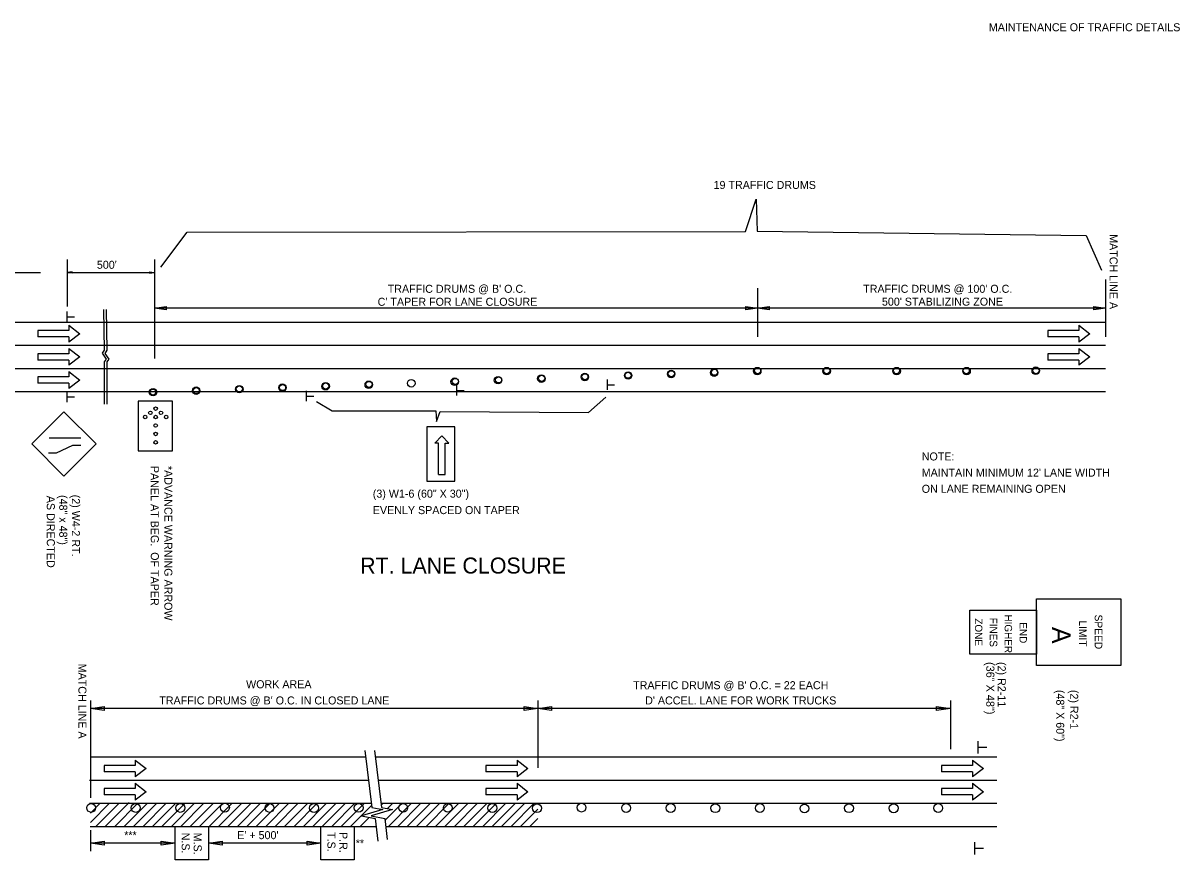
# Model space of a CAD drawing. Extents: x 1373848 to 1374003, y 380642 to 381248.
# Drawn here: x 1373915.2 to 1374001.9, y 381182.7 to 381245.5 of the extents above; entities that cross this region are included whole.
import ezdxf

# ---------------------------------------------------------------- set-up
doc = ezdxf.new("R2010")
doc.units = 0
doc.layers.add('Default', color=7, linetype='Continuous')
doc.layers.add('G-ANNO-TEXT', color=7, linetype='Continuous')

msp = doc.modelspace()

# ---------------------------------------------------------------- linework, layer by layer
at = {"layer": 'Default'}
for p, q in [((1373918.516, 381227.732), (1373918.516, 381224.211)), ((1373925.063, 381227.732), (1373925.063, 381220.318)), ((1373911.3, 381226.753), (1373916.518, 381226.753)), ((1373918.891, 381226.809), (1373918.516, 381226.753)), ((1373918.516, 381226.753), (1373925.063, 381226.753)), ((1373918.891, 381226.697), (1373918.516, 381226.753)), ((1373918.891, 381226.8), (1373918.579, 381226.753)), ((1373918.891, 381226.706), (1373918.579, 381226.753)), ((1373918.891, 381226.79), (1373918.643, 381226.753)), ((1373918.891, 381226.716), (1373918.643, 381226.753)), ((1373918.891, 381226.781), (1373918.706, 381226.753)), ((1373918.891, 381226.725), (1373918.706, 381226.753)), ((1373918.891, 381226.771), (1373918.769, 381226.753)), ((1373918.891, 381226.735), (1373918.769, 381226.753)), ((1373918.891, 381226.762), (1373918.832, 381226.753)), ((1373918.891, 381226.744), (1373918.832, 381226.753)), ((1373918.891, 381226.697), (1373918.891, 381226.809)), ((1373924.688, 381226.809), (1373925.063, 381226.753)), ((1373924.688, 381226.809), (1373924.688, 381226.697)), ((1373924.688, 381226.8), (1373925.001, 381226.753)), ((1373924.688, 381226.79), (1373924.936, 381226.753)), ((1373924.688, 381226.781), (1373924.874, 381226.753)), ((1373924.688, 381226.771), (1373924.81, 381226.753)), ((1373924.688, 381226.762), (1373924.748, 381226.753)), ((1373924.688, 381226.697), (1373925.063, 381226.753)), ((1373924.688, 381226.735), (1373924.81, 381226.753)), ((1373924.688, 381226.716), (1373924.936, 381226.753)), ((1373924.688, 381226.706), (1373925.001, 381226.753)), ((1373924.688, 381226.725), (1373924.874, 381226.753)), ((1373924.688, 381226.744), (1373924.748, 381226.753)), ((1373996.342, 381226.234), (1373996.342, 381221.929)), ((1373925.063, 381225.45), (1373925.063, 381221.929)), ((1373970.264, 381225.585), (1373970.264, 381221.929)), ((1373918.516, 381223.041), (1373918.516, 381223.824)), ((1373925.063, 381224.081), (1373925.933, 381224.212)), ((1373970.264, 381224.081), (1373925.063, 381224.081)), ((1373925.933, 381223.951), (1373925.063, 381224.081)), ((1373925.933, 381224.212), (1373925.933, 381223.951)), ((1373969.395, 381223.951), (1373969.395, 381224.212)), ((1373969.395, 381224.212), (1373970.264, 381224.081)), ((1373970.264, 381224.081), (1373969.395, 381223.951)), ((1373970.264, 381224.081), (1373971.134, 381224.212)), ((1373996.342, 381224.081), (1373970.264, 381224.081)), ((1373971.134, 381223.951), (1373970.264, 381224.081)), ((1373971.134, 381224.212), (1373971.134, 381223.951)), ((1373995.473, 381223.951), (1373995.473, 381224.212)), ((1373995.473, 381224.212), (1373996.342, 381224.081)), ((1373996.342, 381224.081), (1373995.473, 381223.951)), ((1373854.616, 381223.041), (1373996.342, 381223.041)), ((1373918.527, 381223.43), (1373919.062, 381223.43)), ((1373918.658, 381222.804), (1373918.658, 381222.409)), ((1373918.658, 381222.804), (1373919.478, 381222.172)), ((1373994.345, 381222.804), (1373994.345, 381222.409)), ((1373994.345, 381222.804), (1373995.165, 381222.172)), ((1373918.658, 381222.409), (1373916.332, 381222.409)), ((1373916.332, 381222.409), (1373916.332, 381221.935)), ((1373918.658, 381221.935), (1373916.332, 381221.935)), ((1373919.478, 381222.172), (1373918.658, 381221.54)), ((1373918.658, 381221.935), (1373918.658, 381221.54)), ((1373994.345, 381222.409), (1373992.019, 381222.409)), ((1373992.019, 381222.409), (1373992.019, 381221.935)), ((1373994.345, 381221.935), (1373992.019, 381221.935)), ((1373995.165, 381222.172), (1373994.345, 381221.54)), ((1373994.345, 381221.935), (1373994.345, 381221.54)), ((1373854.616, 381221.303), (1373996.342, 381221.303)), ((1373918.658, 381221.066), (1373918.658, 381220.671)), ((1373918.658, 381221.066), (1373919.478, 381220.433)), ((1373994.345, 381221.066), (1373994.345, 381220.671)), ((1373994.345, 381221.066), (1373995.165, 381220.433)), ((1373918.658, 381220.671), (1373916.332, 381220.671)), ((1373916.332, 381220.671), (1373916.332, 381220.196)), ((1373918.658, 381220.196), (1373916.332, 381220.196)), ((1373919.478, 381220.433), (1373918.658, 381219.801)), ((1373918.658, 381220.196), (1373918.658, 381219.801)), ((1373994.345, 381220.671), (1373992.019, 381220.671)), ((1373992.019, 381220.671), (1373992.019, 381220.196)), ((1373994.345, 381220.196), (1373992.019, 381220.196)), ((1373995.165, 381220.433), (1373994.345, 381219.801)), ((1373994.345, 381220.196), (1373994.345, 381219.801)), ((1373854.616, 381219.564), (1373996.342, 381219.564)), ((1373918.658, 381219.327), (1373918.658, 381218.932)), ((1373918.658, 381219.327), (1373919.478, 381218.695)), ((1373918.658, 381218.932), (1373916.332, 381218.932)), ((1373916.332, 381218.932), (1373916.332, 381218.458)), ((1373918.658, 381218.458), (1373916.332, 381218.458)), ((1373919.478, 381218.695), (1373918.658, 381218.063)), ((1373918.658, 381218.458), (1373918.658, 381218.063)), ((1373959.008, 381217.956), (1373959.008, 381218.739)), ((1373854.616, 381217.826), (1373996.342, 381217.826)), ((1373918.516, 381217.043), (1373918.516, 381217.826)), ((1373936.466, 381217.104), (1373936.466, 381217.886)), ((1373947.737, 381217.53), (1373947.737, 381218.312)), ((1373947.748, 381217.919), (1373948.282, 381217.919)), ((1373959.019, 381218.346), (1373959.553, 381218.346)), ((1373918.528, 381217.432), (1373919.062, 381217.432)), ((1373936.477, 381217.493), (1373937.012, 381217.493)), ((1373918.283, 381216.322), (1373915.874, 381213.913)), ((1373918.283, 381216.322), (1373920.693, 381213.913)), ((1373917.167, 381214.376), (1373919.537, 381214.376)), ((1373946.083, 381213.955), (1373946.602, 381214.525)), ((1373946.602, 381214.525), (1373947.121, 381213.955)), ((1373915.874, 381213.913), (1373918.283, 381211.503)), ((1373917.116, 381213.252), (1373917.729, 381213.252)), ((1373917.729, 381213.252), (1373918.954, 381213.814)), ((1373920.693, 381213.913), (1373918.283, 381211.503)), ((1373918.954, 381213.814), (1373919.537, 381213.814)), ((1373946.343, 381213.955), (1373946.083, 381213.955)), ((1373946.343, 381211.625), (1373946.343, 381213.955)), ((1373946.862, 381211.625), (1373946.862, 381213.955)), ((1373946.862, 381213.955), (1373947.121, 381213.955)), ((1373946.343, 381211.625), (1373946.862, 381211.625)), ((1373920.265, 381194.678), (1373920.265, 381187.383)), ((1373920.265, 381194.078), (1373921.296, 381194.232)), ((1373921.296, 381194.232), (1373921.296, 381193.923)), ((1373952.77, 381193.923), (1373952.77, 381194.232)), ((1373952.77, 381194.232), (1373953.8, 381194.078)), ((1373953.8, 381194.678), (1373953.8, 381189.62)), ((1373953.8, 381194.078), (1373954.83, 381194.232)), ((1373954.83, 381194.232), (1373954.83, 381193.923)), ((1373983.68, 381193.923), (1373983.68, 381194.232)), ((1373983.68, 381194.232), (1373984.711, 381194.078)), ((1373984.711, 381194.678), (1373984.711, 381191.026)), ((1373953.8, 381194.078), (1373920.265, 381194.078)), ((1373921.296, 381193.923), (1373920.265, 381194.078)), ((1373953.8, 381194.078), (1373952.77, 381193.923)), ((1373984.711, 381194.078), (1373953.8, 381194.078)), ((1373954.83, 381193.923), (1373953.8, 381194.078)), ((1373984.711, 381194.078), (1373983.68, 381193.923)), ((1373920.265, 381192.487), (1373920.265, 381187.383)), ((1373920.265, 381192.486), (1373920.265, 381187.383)), ((1373920.265, 381192.486), (1373920.265, 381187.383)), ((1373986.797, 381190.701), (1373986.797, 381191.628)), ((1373986.811, 381191.162), (1373987.444, 381191.162)), ((1373920.265, 381190.44), (1373940.88, 381190.44)), ((1373923.614, 381189.808), (1373921.289, 381189.808)), ((1373921.289, 381189.808), (1373921.289, 381189.334)), ((1373923.614, 381190.204), (1373923.614, 381189.808)), ((1373923.614, 381190.204), (1373924.435, 381189.571)), ((1373941.608, 381190.44), (1373953.8, 381190.44)), ((1373952.236, 381189.808), (1373949.91, 381189.808)), ((1373949.91, 381189.808), (1373949.91, 381189.334)), ((1373952.236, 381190.204), (1373952.236, 381189.808)), ((1373952.236, 381190.204), (1373953.057, 381189.571)), ((1373953.8, 381190.44), (1373988.189, 381190.44)), ((1373986.368, 381189.808), (1373984.043, 381189.808)), ((1373984.043, 381189.808), (1373984.043, 381189.334)), ((1373986.368, 381190.204), (1373986.368, 381189.808)), ((1373986.368, 381190.204), (1373987.189, 381189.571)), ((1373923.614, 381189.334), (1373921.289, 381189.334)), ((1373924.435, 381189.571), (1373923.614, 381188.939)), ((1373923.614, 381189.334), (1373923.614, 381188.939)), ((1373952.236, 381189.334), (1373949.91, 381189.334)), ((1373953.057, 381189.571), (1373952.236, 381188.939)), ((1373952.236, 381189.334), (1373952.236, 381188.939)), ((1373986.368, 381189.334), (1373984.043, 381189.334)), ((1373987.189, 381189.571), (1373986.368, 381188.939)), ((1373986.368, 381189.334), (1373986.368, 381188.939)), ((1373920.195, 381188.702), (1373941.097, 381188.702)), ((1373923.614, 381188.07), (1373921.289, 381188.07)), ((1373921.289, 381188.07), (1373921.289, 381187.596)), ((1373923.614, 381188.465), (1373923.614, 381188.07)), ((1373923.614, 381188.465), (1373924.435, 381187.833)), ((1373941.825, 381188.702), (1373953.8, 381188.702)), ((1373952.236, 381188.07), (1373949.91, 381188.07)), ((1373949.91, 381188.07), (1373949.91, 381187.596)), ((1373952.236, 381188.465), (1373952.236, 381188.07)), ((1373952.236, 381188.465), (1373953.057, 381187.833)), ((1373953.8, 381188.702), (1373988.189, 381188.702)), ((1373986.368, 381188.07), (1373984.043, 381188.07)), ((1373984.043, 381188.07), (1373984.043, 381187.596)), ((1373986.368, 381188.465), (1373986.368, 381188.07)), ((1373986.368, 381188.465), (1373987.189, 381187.833)), ((1373923.614, 381187.596), (1373921.289, 381187.596)), ((1373924.435, 381187.833), (1373923.614, 381187.2)), ((1373923.614, 381187.596), (1373923.614, 381187.2)), ((1373952.236, 381187.596), (1373949.91, 381187.596)), ((1373953.057, 381187.833), (1373952.236, 381187.2)), ((1373952.236, 381187.596), (1373952.236, 381187.2)), ((1373986.368, 381187.596), (1373984.043, 381187.596)), ((1373987.189, 381187.833), (1373986.368, 381187.2)), ((1373986.368, 381187.596), (1373986.368, 381187.2)), ((1373920.195, 381186.964), (1373941.314, 381186.964)), ((1373920.266, 381185.524), (1373921.705, 381186.964)), ((1373920.266, 381186.231), (1373920.998, 381186.964)), ((1373920.674, 381185.225), (1373922.412, 381186.964)), ((1373921.381, 381185.225), (1373923.174, 381187.019)), ((1373922.088, 381185.225), (1373923.826, 381186.964)), ((1373922.795, 381185.225), (1373924.533, 381186.964)), ((1373923.502, 381185.225), (1373925.24, 381186.964)), ((1373924.209, 381185.225), (1373925.948, 381186.964)), ((1373924.916, 381185.225), (1373926.655, 381186.964)), ((1373925.623, 381185.225), (1373927.362, 381186.964)), ((1373926.331, 381185.225), (1373928.069, 381186.964)), ((1373927.038, 381185.225), (1373928.776, 381186.964)), ((1373927.745, 381185.225), (1373929.483, 381186.964)), ((1373928.452, 381185.225), (1373930.19, 381186.964)), ((1373929.159, 381185.225), (1373930.897, 381186.964)), ((1373929.866, 381185.225), (1373931.604, 381186.964)), ((1373930.573, 381185.225), (1373932.311, 381186.964)), ((1373931.28, 381185.225), (1373933.019, 381186.964)), ((1373931.987, 381185.225), (1373933.726, 381186.964)), ((1373932.695, 381185.225), (1373934.433, 381186.964)), ((1373933.402, 381185.225), (1373935.14, 381186.964)), ((1373934.109, 381185.225), (1373935.847, 381186.964)), ((1373934.816, 381185.225), (1373936.554, 381186.964)), ((1373935.523, 381185.225), (1373937.261, 381186.964)), ((1373936.23, 381185.225), (1373937.968, 381186.964)), ((1373936.937, 381185.225), (1373938.675, 381186.964)), ((1373937.644, 381185.225), (1373939.383, 381186.964)), ((1373938.351, 381185.225), (1373940.09, 381186.964)), ((1373939.058, 381185.225), (1373940.797, 381186.964)), ((1373939.766, 381185.225), (1373941.335, 381186.795)), ((1373942.043, 381186.964), (1373953.8, 381186.964)), ((1373942.061, 381186.814), (1373942.211, 381186.964)), ((1373942.342, 381185.68), (1373943.625, 381186.964)), ((1373942.524, 381186.57), (1373942.918, 381186.964)), ((1373942.594, 381185.225), (1373944.332, 381186.964)), ((1373943.301, 381185.225), (1373945.039, 381186.964)), ((1373944.008, 381185.225), (1373945.746, 381186.964)), ((1373944.715, 381185.225), (1373946.454, 381186.964)), ((1373945.422, 381185.225), (1373947.161, 381186.964)), ((1373946.13, 381185.225), (1373947.868, 381186.964)), ((1373946.837, 381185.225), (1373948.575, 381186.964)), ((1373947.544, 381185.225), (1373949.282, 381186.964)), ((1373948.251, 381185.225), (1373949.989, 381186.964)), ((1373948.958, 381185.225), (1373950.696, 381186.964)), ((1373949.665, 381185.225), (1373951.403, 381186.964)), ((1373950.372, 381185.225), (1373952.11, 381186.964)), ((1373951.079, 381185.225), (1373952.818, 381186.964)), ((1373951.786, 381185.225), (1373953.525, 381186.964)), ((1373952.494, 381185.225), (1373953.801, 381186.532)), ((1373953.8, 381186.964), (1373988.189, 381186.964)), ((1373940.473, 381185.225), (1373941.154, 381185.906)), ((1373953.201, 381185.225), (1373953.801, 381185.825)), ((1373920.243, 381185.225), (1373941.668, 381185.225)), ((1373920.265, 381184.959), (1373920.265, 381183.383)), ((1373942.397, 381185.225), (1373953.8, 381185.225)), ((1373953.8, 381185.225), (1373988.189, 381185.225)), ((1373920.265, 381183.975), (1373921.296, 381184.13)), ((1373926.607, 381183.975), (1373920.265, 381183.975)), ((1373921.296, 381183.82), (1373920.265, 381183.975)), ((1373921.296, 381184.13), (1373921.296, 381183.82)), ((1373925.577, 381183.82), (1373925.577, 381184.13)), ((1373925.577, 381184.13), (1373926.607, 381183.975)), ((1373926.607, 381183.975), (1373925.577, 381183.82)), ((1373929.107, 381183.975), (1373930.138, 381184.13)), ((1373937.528, 381183.975), (1373929.107, 381183.975)), ((1373930.138, 381183.82), (1373929.107, 381183.975)), ((1373930.138, 381184.13), (1373930.138, 381183.82)), ((1373936.498, 381183.82), (1373936.498, 381184.13)), ((1373936.498, 381184.13), (1373937.528, 381183.975)), ((1373937.528, 381183.975), (1373936.498, 381183.82)), ((1373986.557, 381183.136), (1373986.557, 381184.063)), ((1373986.571, 381183.597), (1373987.204, 381183.597))]:
    msp.add_line(p, q, dxfattribs=at)
for points in [[(1373925.55, 381227.166), (1373927.525, 381229.784), (1373969.351, 381229.832), (1373970.157, 381232.251), (1373970.229, 381229.867), (1373994.898, 381229.533), (1373996.039, 381226.936)], [(1373921.252, 381223.977), (1373921.298, 381220.946), (1373921.136, 381220.704), (1373921.452, 381220.271), (1373921.286, 381220.071), (1373921.285, 381216.89)], [(1373921.452, 381223.977), (1373921.498, 381220.937), (1373921.336, 381220.696), (1373921.652, 381220.263), (1373921.486, 381220.063), (1373921.485, 381216.89)], [(1373937.218, 381217.083), (1373938.376, 381216.401), (1373946.142, 381216.401), (1373946.21, 381215.583), (1373946.482, 381216.333), (1373957.585, 381216.265), (1373958.88, 381217.424)], [(1373940.819, 381190.924), (1373941.354, 381186.648), (1373942.179, 381186.502), (1373940.577, 381186.016), (1373941.596, 381185.822), (1373941.799, 381184.137)], [(1373941.548, 381190.924), (1373942.082, 381186.648), (1373942.907, 381186.502), (1373941.305, 381186.016), (1373942.325, 381185.822), (1373942.515, 381184.241)]]:
    msp.add_lwpolyline(points, dxfattribs=at)
for points in [[(1373923.838, 381217.112), (1373923.838, 381213.388), (1373926.414, 381213.388), (1373926.414, 381217.112)], [(1373945.489, 381215.19), (1373945.489, 381211.104), (1373947.579, 381211.104), (1373947.579, 381215.19)], [(1373997.476, 381197.297), (1373991.174, 381197.297), (1373991.174, 381202.297), (1373997.476, 381202.297)], [(1373991.174, 381198.138), (1373986.172, 381198.138), (1373986.172, 381201.456), (1373991.174, 381201.456)], [(1373926.607, 381185.225), (1373929.107, 381185.225), (1373929.107, 381182.725), (1373926.607, 381182.725)], [(1373937.528, 381185.225), (1373940.028, 381185.225), (1373940.028, 381182.725), (1373937.528, 381182.725)]]:
    msp.add_lwpolyline(points, close=True, dxfattribs=at)
for centre, radius in [((1373960.565, 381219.035), 0.281), ((1373960.561, 381219.055), 0.229), ((1373963.786, 381219.145), 0.281), ((1373963.798, 381219.169), 0.229), ((1373967.011, 381219.256), 0.281), ((1373967.034, 381219.284), 0.229), ((1373970.236, 381219.367), 0.281), ((1373970.259, 381219.4), 0.229), ((1373970.271, 381219.399), 0.229), ((1373975.44, 381219.367), 0.281), ((1373975.448, 381219.397), 0.229), ((1373980.683, 381219.367), 0.281), ((1373980.675, 381219.397), 0.229), ((1373985.925, 381219.367), 0.281), ((1373985.902, 381219.397), 0.229), ((1373991.112, 381219.394), 0.281), ((1373991.129, 381219.397), 0.229), ((1373934.658, 381218.122), 0.281), ((1373937.892, 381218.232), 0.281), ((1373937.903, 381218.252), 0.229), ((1373941.125, 381218.343), 0.281), ((1373941.14, 381218.367), 0.229), ((1373944.314, 381218.453), 0.281), ((1373947.564, 381218.57), 0.281), ((1373947.614, 381218.596), 0.229), ((1373950.814, 381218.686), 0.281), ((1373950.85, 381218.711), 0.229), ((1373954.064, 381218.802), 0.281), ((1373954.087, 381218.825), 0.229), ((1373957.315, 381218.919), 0.281), ((1373957.324, 381218.94), 0.229), ((1373924.958, 381217.789), 0.281), ((1373924.944, 381217.794), 0.229), ((1373924.956, 381217.793), 0.229), ((1373928.191, 381217.9), 0.281), ((1373928.193, 381217.908), 0.229), ((1373931.425, 381218.011), 0.281), ((1373931.43, 381218.023), 0.229), ((1373934.666, 381218.137), 0.229), ((1373925.155, 381216.554), 0.131), ((1373924.366, 381215.921), 0.131), ((1373924.761, 381216.237), 0.131), ((1373925.155, 381215.921), 0.131), ((1373925.55, 381216.237), 0.131), ((1373925.944, 381215.921), 0.131), ((1373925.155, 381215.289), 0.131), ((1373925.155, 381214.656), 0.131), ((1373925.155, 381214.024), 0.131), ((1373920.32, 381186.621), 0.333), ((1373923.661, 381186.621), 0.333), ((1373927.003, 381186.622), 0.333), ((1373930.344, 381186.642), 0.333), ((1373933.685, 381186.621), 0.333), ((1373937.026, 381186.61), 0.333), ((1373940.367, 381186.626), 0.333), ((1373943.708, 381186.626), 0.333), ((1373947.049, 381186.626), 0.333), ((1373950.39, 381186.611), 0.333), ((1373953.731, 381186.598), 0.333), ((1373957.072, 381186.646), 0.333), ((1373960.413, 381186.614), 0.333), ((1373963.754, 381186.614), 0.333), ((1373967.095, 381186.598), 0.333), ((1373970.436, 381186.612), 0.333), ((1373973.777, 381186.576), 0.333), ((1373977.118, 381186.598), 0.333), ((1373980.459, 381186.595), 0.333), ((1373983.8, 381186.611), 0.333)]:
    msp.add_circle(centre, radius, dxfattribs=at)

# ---------------------------------------------------------------- texts
for s, height, p in [('19 TRAFFIC DRUMS', 0.6, (1373966.966, 381233.023)), ("500'", 0.6, (1373920.749, 381227.038)), ("TRAFFIC DRUMS @ B' O.C.", 0.6, (1373942.547, 381225.237)), ("TRAFFIC DRUMS @ 100' O.C.", 0.6, (1373978.178, 381225.237)), ("C' TAPER FOR LANE CLOSURE", 0.6, (1373941.791, 381224.264)), ("500' STABILIZING ZONE", 0.6, (1373979.583, 381224.274)), ('NOTE:', 0.6, (1373982.566, 381212.669)), ("MAINTAIN MINIMUM 12' LANE WIDTH", 0.6, (1373982.566, 381211.456)), ('ON LANE REMAINING OPEN', 0.6, (1373982.566, 381210.243)), ('RT. LANE CLOSURE', 1.2, (1373940.475, 381204.19)), ('WORK AREA', 0.6, (1373931.932, 381195.592)), ("TRAFFIC DRUMS @ B' O.C. = 22 EACH", 0.6, (1373960.937, 381195.52)), ("TRAFFIC DRUMS @ B' O.C. IN CLOSED LANE", 0.6, (1373925.428, 381194.378)), ("D' ACCEL. LANE FOR WORK TRUCKS", 0.6, (1373961.837, 381194.378)), ('***', 0.6, (1373922.798, 381184.278)), ("E' + 500'", 0.6, (1373931.267, 381184.278)), ('**', 0.6, (1373940.151, 381183.675))]:
    msp.add_text(s, height=height, dxfattribs=at).set_placement(p)
for s, height, rotation, p in [('MATCH LINE A', 0.6, 270, (1373996.642, 381229.63)), ('PANEL AT BEG.  OF TAPER', 0.6, 270, (1373924.792, 381212.257)), ('*ADVANCE WARNING ARROW', 0.6, 270, (1373925.804, 381212.257)), ('AS DIRECTED ', 0.6, 270, (1373916.998, 381210.019)), ('(48" x 48")', 0.6, 270, (1373917.929, 381210.075)), ('(2) W4-2 RT.', 0.6, 270, (1373918.879, 381210.1)), ('(3) W1-6 (60" X 30")', 0.6, 0.00754, (1373941.427, 381209.88)), ('EVENLY SPACED ON TAPER', 0.6, 0.00754, (1373941.427, 381208.645)), ('HIGHER', 0.5566, 270, (1373988.779, 381201.125)), ('SPEED', 0.5729, 270, (1373995.529, 381201.116)), ('ZONE', 0.5566, 270, (1373986.552, 381200.83)), ('FINES', 0.5566, 270, (1373987.666, 381200.88)), ('END', 0.5566, 270, (1373989.892, 381200.533)), ('LIMIT', 0.5729, 270, (1373994.358, 381200.673)), ('A', 1.396, 270, (1373992.336, 381200.188)), ('MATCH LINE A', 0.6, 270, (1373919.365, 381197.434)), ('(36" X 48")', 0.61, 270, (1373987.401, 381197.558)), ('(2) R2-11', 0.6, 270, (1373988.264, 381197.558)), ('(48" X 60")', 0.6, 270, (1373992.644, 381195.468)), ('(2) R2-1', 0.6, 270, (1373993.69, 381195.468)), ('N.S.', 0.6, 270, (1373927.107, 381184.766)), ('M.S.', 0.6, 270, (1373928.007, 381184.766)), ('T.S.', 0.6, 270, (1373938.028, 381184.814)), ('P.R.', 0.6, 270, (1373938.928, 381184.814))]:
    msp.add_text(s, height=height, rotation=rotation, dxfattribs=at).set_placement(p)
at = {"layer": 'G-ANNO-TEXT'}
msp.add_text('MAINTENANCE OF TRAFFIC DETAILS', height=0.6, dxfattribs=at).set_placement((1373987.593, 381244.845))

doc.saveas('drawing.dxf')
